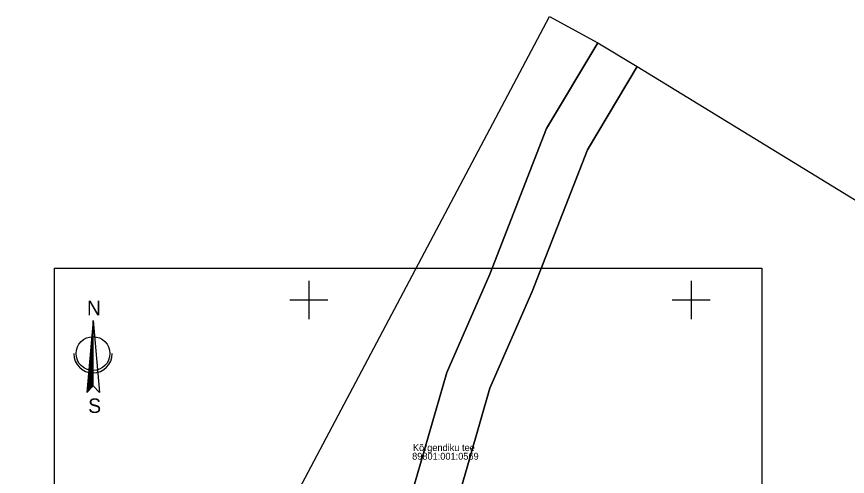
# Model space of a CAD drawing. Extents: x 598011 to 598230, y 6478330 to 6478537.
# Drawn here: x 598011.8 to 598120.4, y 6478476.9 to 6478537 of the extents above; entities that cross this region are included whole.
import ezdxf

# ---------------------------------------------------------------- set-up
doc = ezdxf.new("R2010")
doc.units = 0
for name, color, linetype in [('PIIR', 7, 'Continuous'), ('VORK', 7, 'Continuous'), ('VORMISTUS', 7, 'Continuous')]:
    doc.layers.add(name, color=color, linetype=linetype)

msp = doc.modelspace()

# ---------------------------------------------------------------- linework, layer by layer
at = {"layer": 'PIIR'}
for points in [[(598011.79, 6478405.5), (598081.48, 6478537.03), (598087.81, 6478533.61), (598081.1, 6478522.41), (598073.68, 6478503.38), (598068.04, 6478490.52), (598063.74, 6478475.61), (598063.42, 6478466.37), (598055.37, 6478465.26), (598054.72, 6478435.22), (598057.87, 6478421.2), (598067.5, 6478424), (598075.6, 6478425.87), (598075.95, 6478425.95), (598080.86, 6478427.08), (598083.16, 6478418.05), (598077.61, 6478417.15), (598069.31, 6478414.97), (598050.5, 6478410.56), (598053.52, 6478386.1), (598055.7, 6478377.93), (598019.25, 6478379.83)], [(598081.1, 6478522.41), (598087.81, 6478533.61), (598092.94, 6478530.49), (598086.45, 6478519.6), (598079.22, 6478501.09), (598073.69, 6478488.47), (598069.71, 6478474.66), (598069.29, 6478462.69), (598071.55, 6478454.2), (598077.2, 6478441.43), (598080.86, 6478427.08), (598075.95, 6478425.95), (598072.84, 6478439.42), (598065.87, 6478452.21), (598063.26, 6478462.01), (598063.42, 6478466.37), (598063.74, 6478475.61), (598068.04, 6478490.52), (598073.68, 6478503.38)], [(598093.38, 6478381.19), (598086.49, 6478418.82), (598083.16, 6478418.05), (598080.86, 6478427.08), (598077.2, 6478441.43), (598071.55, 6478454.2), (598069.29, 6478462.69), (598069.71, 6478474.66), (598073.69, 6478488.47), (598079.22, 6478501.09), (598086.45, 6478519.6), (598092.94, 6478530.49), (598127.2, 6478509.56), (598154.27, 6478492.13), (598192.62, 6478466.21), (598223.81, 6478441.55), (598229.65, 6478435.94), (598191.25, 6478412.44), (598173.37, 6478396.18), (598161.58, 6478385.58), (598151.68, 6478381.11), (598144.54, 6478375.38)]]:
    msp.add_lwpolyline(points, close=True, dxfattribs=at)
at = {"layer": 'VORK'}
for p, q in [((598050, 6478502.5), (598050, 6478497.5)), ((598100, 6478502.5), (598100, 6478497.5)), ((598047.5, 6478500), (598052.5, 6478500)), ((598097.5, 6478500), (598102.5, 6478500))]:
    msp.add_line(p, q, dxfattribs=at)
at = {"layer": 'VORMISTUS'}
for p, q in [((598021.78, 6478497.33), (598020.96, 6478487.91)), ((598021.7, 6478496.42), (598021.78, 6478496.42)), ((598021.71, 6478496.52), (598021.78, 6478496.52)), ((598021.72, 6478496.61), (598021.78, 6478496.61)), ((598021.73, 6478496.7), (598021.78, 6478496.7)), ((598021.74, 6478496.89), (598021.78, 6478496.89)), ((598021.74, 6478496.8), (598021.78, 6478496.8)), ((598021.75, 6478496.99), (598021.78, 6478496.99)), ((598021.76, 6478497.08), (598021.78, 6478497.08)), ((598021.77, 6478497.18), (598021.78, 6478497.18)), ((598021.78, 6478497.33), (598022.61, 6478487.91)), ((598021.78, 6478488.79), (598021.78, 6478497.33)), ((598021.78, 6478497.27), (598021.78, 6478497.27)), ((598021.61, 6478495.38), (598021.78, 6478495.38)), ((598021.62, 6478495.47), (598021.78, 6478495.47)), ((598021.63, 6478495.57), (598021.78, 6478495.57)), ((598021.64, 6478495.76), (598021.78, 6478495.76)), ((598021.64, 6478495.66), (598021.78, 6478495.66)), ((598021.65, 6478495.85), (598021.78, 6478495.85)), ((598021.66, 6478495.95), (598021.78, 6478495.95)), ((598021.67, 6478496.04), (598021.78, 6478496.04)), ((598021.68, 6478496.14), (598021.78, 6478496.14)), ((598021.69, 6478496.33), (598021.78, 6478496.33)), ((598021.69, 6478496.23), (598021.78, 6478496.23)), ((598021.51, 6478494.24), (598021.78, 6478494.24)), ((598021.52, 6478494.34), (598021.78, 6478494.34)), ((598021.53, 6478494.43), (598021.78, 6478494.43)), ((598021.54, 6478494.53), (598021.78, 6478494.53)), ((598021.55, 6478494.72), (598021.78, 6478494.72)), ((598021.55, 6478494.62), (598021.78, 6478494.62)), ((598021.56, 6478494.81), (598021.78, 6478494.81)), ((598021.57, 6478494.91), (598021.78, 6478494.91)), ((598021.58, 6478495), (598021.78, 6478495)), ((598021.59, 6478495.1), (598021.78, 6478495.1)), ((598021.6, 6478495.29), (598021.78, 6478495.29)), ((598021.6, 6478495.19), (598021.78, 6478495.19)), ((598021.42, 6478493.2), (598021.78, 6478493.2)), ((598021.43, 6478493.3), (598021.78, 6478493.3)), ((598021.44, 6478493.39), (598021.78, 6478493.39)), ((598021.45, 6478493.58), (598021.78, 6478493.58)), ((598021.45, 6478493.49), (598021.78, 6478493.49)), ((598021.46, 6478493.68), (598021.78, 6478493.68)), ((598021.47, 6478493.77), (598021.78, 6478493.77)), ((598021.48, 6478493.87), (598021.78, 6478493.87)), ((598021.49, 6478493.96), (598021.78, 6478493.96)), ((598021.5, 6478494.15), (598021.78, 6478494.15)), ((598021.5, 6478494.06), (598021.78, 6478494.06)), ((598021.32, 6478492.07), (598021.78, 6478492.07)), ((598021.33, 6478492.16), (598021.78, 6478492.16)), ((598021.34, 6478492.26), (598021.78, 6478492.26)), ((598021.35, 6478492.35), (598021.78, 6478492.35)), ((598021.36, 6478492.54), (598021.78, 6478492.54)), ((598021.36, 6478492.45), (598021.78, 6478492.45)), ((598021.37, 6478492.64), (598021.78, 6478492.64)), ((598021.38, 6478492.73), (598021.78, 6478492.73)), ((598021.39, 6478492.83), (598021.78, 6478492.83)), ((598021.4, 6478493.01), (598021.78, 6478493.01)), ((598021.4, 6478492.92), (598021.78, 6478492.92)), ((598021.41, 6478493.11), (598021.78, 6478493.11)), ((598021.23, 6478491.03), (598021.78, 6478491.03)), ((598021.24, 6478491.12), (598021.78, 6478491.12)), ((598021.25, 6478491.22), (598021.78, 6478491.22)), ((598021.26, 6478491.41), (598021.78, 6478491.41)), ((598021.26, 6478491.31), (598021.78, 6478491.31)), ((598021.27, 6478491.5), (598021.78, 6478491.5)), ((598021.28, 6478491.6), (598021.78, 6478491.6)), ((598021.29, 6478491.69), (598021.78, 6478491.69)), ((598021.3, 6478491.78), (598021.78, 6478491.78)), ((598021.31, 6478491.97), (598021.78, 6478491.97)), ((598021.31, 6478491.88), (598021.78, 6478491.88)), ((598021.13, 6478489.89), (598021.78, 6478489.89)), ((598021.14, 6478489.99), (598021.78, 6478489.99)), ((598021.15, 6478490.08), (598021.78, 6478490.08)), ((598021.16, 6478490.27), (598021.78, 6478490.27)), ((598021.16, 6478490.18), (598021.78, 6478490.18)), ((598021.17, 6478490.37), (598021.78, 6478490.37)), ((598021.18, 6478490.46), (598021.78, 6478490.46)), ((598021.19, 6478490.55), (598021.78, 6478490.55)), ((598021.2, 6478490.65), (598021.78, 6478490.65)), ((598021.21, 6478490.84), (598021.78, 6478490.84)), ((598021.21, 6478490.74), (598021.78, 6478490.74)), ((598021.22, 6478490.93), (598021.78, 6478490.93)), ((598020.96, 6478487.91), (598021.78, 6478488.79)), ((598021.04, 6478488.85), (598021.78, 6478488.85)), ((598021.05, 6478488.95), (598021.78, 6478488.95)), ((598021.06, 6478489.04), (598021.78, 6478489.04)), ((598021.07, 6478489.23), (598021.78, 6478489.23)), ((598021.07, 6478489.14), (598021.78, 6478489.14)), ((598021.08, 6478489.32), (598021.78, 6478489.32)), ((598021.09, 6478489.42), (598021.78, 6478489.42)), ((598021.1, 6478489.51), (598021.78, 6478489.51)), ((598021.11, 6478489.61), (598021.78, 6478489.61)), ((598021.12, 6478489.8), (598021.78, 6478489.8)), ((598021.12, 6478489.7), (598021.78, 6478489.7)), ((598021.78, 6478488.79), (598022.61, 6478487.91)), ((598020.97, 6478488.09), (598021.13, 6478488.09)), ((598020.97, 6478488), (598021.04, 6478488)), ((598020.98, 6478488.19), (598021.22, 6478488.19)), ((598020.99, 6478488.28), (598021.31, 6478488.28)), ((598021, 6478488.38), (598021.4, 6478488.38)), ((598021.01, 6478488.47), (598021.48, 6478488.47)), ((598021.02, 6478488.66), (598021.66, 6478488.66)), ((598021.02, 6478488.57), (598021.57, 6478488.57)), ((598021.03, 6478488.76), (598021.75, 6478488.76))]:
    msp.add_line(p, q, dxfattribs=at)
msp.add_lwpolyline([(598109.25, 6478361.64), (598016.75, 6478361.64), (598016.75, 6478504.14), (598109.25, 6478504.14), (598109.25, 6478361.64)], dxfattribs=at)
msp.add_circle((598021.78, 6478492.99), 2.21, dxfattribs=at)
msp.add_arc((598021.78, 6478492.99), 2.52, 180, 0, dxfattribs=at)

# ---------------------------------------------------------------- texts
at = {"layer": 'PIIR'}
for s, p in [('Kõrgendiku tee', (598063.61, 6478480.25)), ('89801:001:0569', (598063.51, 6478479.12))]:
    msp.add_text(s, height=0.9, dxfattribs=at).set_placement(p)
at = {"layer": 'VORMISTUS'}
for s, p in [('N', (598020.99, 6478498)), ('S', (598021.15, 6478485.23))]:
    msp.add_text(s, height=1.89, dxfattribs=at).set_placement(p)

doc.saveas('drawing.dxf')
